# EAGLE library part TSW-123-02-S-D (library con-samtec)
THROUGH-HOLE .025" SQ POST HEADER Source: Samtec TSW.pdf
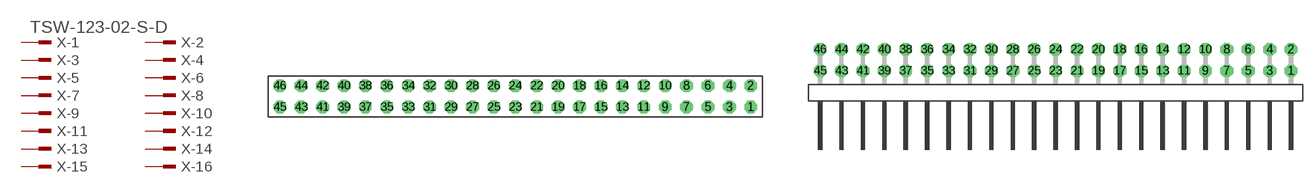
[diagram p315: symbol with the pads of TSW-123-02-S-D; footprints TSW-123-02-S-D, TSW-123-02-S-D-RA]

Designator prefix X; gates -1=MPINV -2=MPIN -3=MPIN -4=MPIN -5=MPIN -6=MPIN -7=MPIN -8=MPIN -9=MPIN -10=MPIN -11=MPIN -12=MPIN -13=MPIN -14=MPIN -15=MPIN -16=MPIN -17=MPIN -18=MPIN -19=MPIN -20=MPIN -21=MPIN -22=MPIN -23=MPIN -24=MPIN -25=MPIN -26=MPIN -27=MPIN -28=MPIN -29=MPIN -30=MPIN -31=MPIN -32=MPIN -33=MPIN -34=MPIN -35=MPIN -36=MPIN -37=MPIN -38=MPIN -39=MPIN -40=MPIN -41=MPIN -42=MPIN -43=MPIN -44=MPIN -45=MPIN -46=MPIN

## TSW-123-02-S-D (OC_FARNELL: unknown; OC_NEWARK: unknown)  [TSW-123-02-S-D]
1  -1:1  pas
2  -2:1  pas
3  -3:1  pas
4  -4:1  pas
5  -5:1  pas
6  -6:1  pas
7  -7:1  pas
8  -8:1  pas
9  -9:1  pas
10  -10:1  pas
11  -11:1  pas
12  -12:1  pas
13  -13:1  pas
14  -14:1  pas
15  -15:1  pas
16  -16:1  pas
17  -17:1  pas
18  -18:1  pas
19  -19:1  pas
20  -20:1  pas
21  -21:1  pas
22  -22:1  pas
23  -23:1  pas
24  -24:1  pas
25  -25:1  pas
26  -26:1  pas
27  -27:1  pas
28  -28:1  pas
29  -29:1  pas
30  -30:1  pas
31  -31:1  pas
32  -32:1  pas
33  -33:1  pas
34  -34:1  pas
35  -35:1  pas
36  -36:1  pas
37  -37:1  pas
38  -38:1  pas
39  -39:1  pas
40  -40:1  pas
41  -41:1  pas
42  -42:1  pas
43  -43:1  pas
44  -44:1  pas
45  -45:1  pas
46  -46:1  pas

## TSW-123-02-S-D-RA (OC_FARNELL: unknown; OC_NEWARK: unknown)  [TSW-123-02-S-D-RA]
Pads as for TSW-123-02-S-D

## Footprint TSW-123-02-S-D (pad centres in mm)
THROUGH-HOLE .025" SQ POST HEADER Source: Samtec TSW.pdf
drill 1 pad 1.5 octagon: 1 27.94,-1.27; 2 27.94,1.27; 3 25.4,-1.27; 4 25.4,1.27; 5 22.86,-1.27; 6 22.86,1.27; 7 20.32,-1.27; 8 20.32,1.27; 9 17.78,-1.27; 10 17.78,1.27; 11 15.24,-1.27; 12 15.24,1.27; 13 12.7,-1.27; 14 12.7,1.27; 15 10.16,-1.27; 16 10.16,1.27; 17 7.62,-1.27; 18 7.62,1.27; 19 5.08,-1.27; 20 5.08,1.27; 21 2.54,-1.27; 22 2.54,1.27; 23 0,-1.27; 24 0,1.27; 25 -2.54,-1.27; 26 -2.54,1.27; 27 -5.08,-1.27; 28 -5.08,1.27; 29 -7.62,-1.27; 30 -7.62,1.27; 31 -10.16,-1.27; 32 -10.16,1.27; 33 -12.7,-1.27; 34 -12.7,1.27; 35 -15.24,-1.27; 36 -15.24,1.27; 37 -17.78,-1.27; 38 -17.78,1.27; 39 -20.32,-1.27; 40 -20.32,1.27; 41 -22.86,-1.27; 42 -22.86,1.27; 43 -25.4,-1.27; 44 -25.4,1.27; 45 -27.94,-1.27; 46 -27.94,1.27

## Footprint TSW-123-02-S-D-RA (pad centres in mm)
THROUGH-HOLE .025" SQ POST HEADER Source: Samtec TSW.pdf
drill 1 pad 1.5 octagon: 1 27.94,1.524; 2 27.94,4.064; 3 25.4,1.524; 4 25.4,4.064; 5 22.86,1.524; 6 22.86,4.064; 7 20.32,1.524; 8 20.32,4.064; 9 17.78,1.524; 10 17.78,4.064; 11 15.24,1.524; 12 15.24,4.064; 13 12.7,1.524; 14 12.7,4.064; 15 10.16,1.524; 16 10.16,4.064; 17 7.62,1.524; 18 7.62,4.064; 19 5.08,1.524; 20 5.08,4.064; 21 2.54,1.524; 22 2.54,4.064; 23 0,1.524; 24 0,4.064; 25 -2.54,1.524; 26 -2.54,4.064; 27 -5.08,1.524; 28 -5.08,4.064; 29 -7.62,1.524; 30 -7.62,4.064; 31 -10.16,1.524; 32 -10.16,4.064; 33 -12.7,1.524; 34 -12.7,4.064; 35 -15.24,1.524; 36 -15.24,4.064; 37 -17.78,1.524; 38 -17.78,4.064; 39 -20.32,1.524; 40 -20.32,4.064; 41 -22.86,1.524; 42 -22.86,4.064; 43 -25.4,1.524; 44 -25.4,4.064; 45 -27.94,1.524; 46 -27.94,4.064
